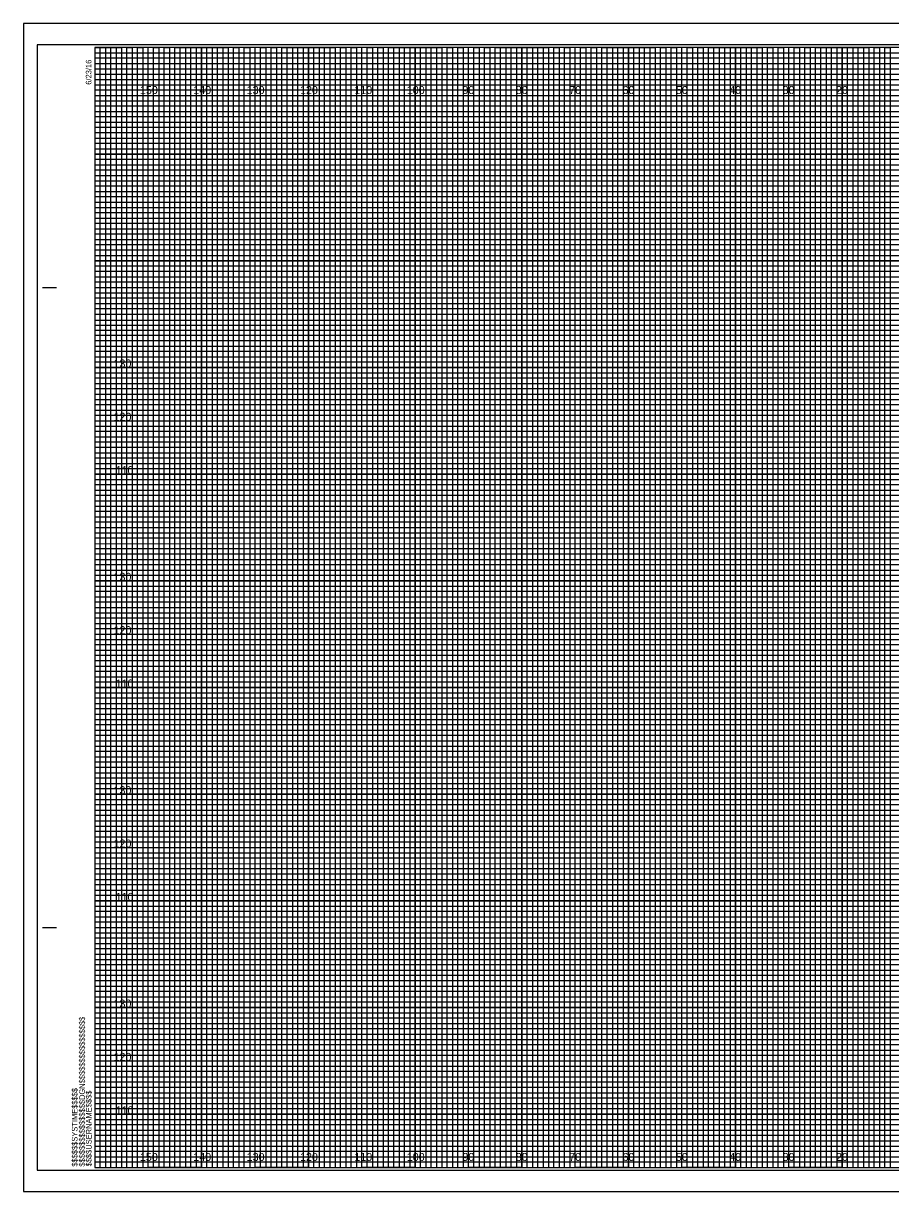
# Model space of a CAD drawing. Extents: x -13 to 323, y -5 to 215.
# Drawn here: x -13.4 to 149.1, y -4.5 to 214.5 of the extents above; entities that cross this region are included whole.
import ezdxf

# ---------------------------------------------------------------- set-up
doc = ezdxf.new("R2010")
doc.units = 0
for name, color, linetype in [('Prop XS Elevation Labels', 7, 'Continuous'), ('Prop XS Offset Labels', 7, 'Continuous'), ('Sheet Cross Section CELL', 7, 'Continuous'), ('Sheet Cross Section Grid Major CELL', 7, 'Continuous'), ('Sheet Cross Section Grid Middle CELL', 7, 'Continuous'), ('Sheet Cross Section Grid Minor 1 CELL', 7, 'Continuous'), ('Sheet Cross Section Grid Minor 2 CELL', 7, 'Continuous'), ('Sheet Cutting Line CELL', 7, 'Continuous'), ('Sheet DOT Grid CELL', 7, 'Continuous'), ('Sheet Plot Border Inside CELL', 7, 'Continuous'), ('Sheet Plot Border Outside CELL', 7, 'Continuous')]:
    doc.layers.add(name, color=color, linetype=linetype)

msp = doc.modelspace()

# ---------------------------------------------------------------- linework, layer by layer
at = {"layer": 'Sheet Cross Section CELL'}
for p, q in [((-9.8, 165), (-7.3, 165)), ((-9.7, 165), (-7.2, 165)), ((-9.8, 45), (-7.3, 45)), ((-9.7, 45), (-7.2, 45)), ((0, 0), (0, 0)), ((0, 0), (0, 0)), ((0, 0), (0, 0)), ((0, 0), (0, 0)), ((0, 0), (0, 0)), ((0, 0), (0, 0)), ((0, 0), (0, 0))]:
    msp.add_line(p, q, dxfattribs=at)
msp.add_lwpolyline([(320, 210), (0, 210), (0, 0), (320, 0)], close=True, dxfattribs=at)
at = {"layer": 'Sheet Cross Section Grid Major CELL'}
for p, q in [((10, 210), (0, 210)), ((10, 0), (10, 210)), ((30, 210), (20, 210)), ((20, 210), (20, 0)), ((30, 0), (30, 210)), ((50, 210), (40, 210)), ((40, 210), (40, 0)), ((50, 0), (50, 210)), ((70, 210), (60, 210)), ((60, 210), (60, 0)), ((70, 0), (70, 210)), ((90, 210), (80, 210)), ((80, 210), (80, 0)), ((90, 0), (90, 210)), ((110, 210), (100, 210)), ((100, 210), (100, 0)), ((110, 0), (110, 210)), ((130, 210), (120, 210)), ((120, 210), (120, 0)), ((130, 0), (130, 210)), ((150, 210), (140, 210)), ((140, 210), (140, 0)), ((20, 0), (10, 0)), ((40, 0), (30, 0)), ((60, 0), (50, 0)), ((80, 0), (70, 0)), ((100, 0), (90, 0)), ((120, 0), (110, 0)), ((140, 0), (130, 0))]:
    msp.add_line(p, q, dxfattribs=at)
for points in [[(0, 200), (320, 200), (320, 190), (0, 190)], [(0, 180), (320, 180), (320, 170), (0, 170)], [(0, 160), (320, 160), (320, 150), (0, 150)], [(0, 140), (320, 140), (320, 130), (0, 130)], [(0, 120), (320, 120), (320, 110), (0, 110)], [(0, 100), (320, 100), (320, 90), (0, 90)], [(0, 80), (320, 80), (320, 70), (0, 70)], [(0, 60), (320, 60), (320, 50), (0, 50)], [(0, 40), (320, 40), (320, 30), (0, 30)], [(0, 20), (320, 20), (320, 10), (0, 10)]]:
    msp.add_lwpolyline(points, dxfattribs=at)
at = {"layer": 'Sheet Cross Section Grid Middle CELL'}
for points in [[(0, 210), (5, 210), (5, 0), (15, 0), (15, 210), (25, 210), (25, 0), (35, 0), (35, 210), (45, 210), (45, 0), (55, 0), (55, 210), (65, 210), (65, 0), (75, 0), (75, 210), (85, 210), (85, 0), (95, 0), (95, 210), (105, 210), (105, 0), (115, 0), (115, 210), (125, 210), (125, 0), (135, 0), (135, 210), (145, 210), (145, 0), (155, 0)], [(0, 205), (275, 205)], [(0, 185), (320, 185), (320, 195), (0, 195)], [(0, 165), (320, 165), (320, 175), (0, 175)], [(0, 145), (320, 145), (320, 155), (0, 155)], [(0, 125), (320, 125), (320, 135), (0, 135)], [(0, 105), (320, 105), (320, 115), (0, 115)], [(0, 85), (320, 85), (320, 95), (0, 95)], [(0, 65), (320, 65), (320, 75), (0, 75)], [(0, 45), (320, 45), (320, 55), (0, 55)], [(0, 25), (320, 25), (320, 35), (0, 35)], [(0, 5), (320, 5), (320, 15), (0, 15)]]:
    msp.add_lwpolyline(points, dxfattribs=at)
at = {"layer": 'Sheet Cross Section Grid Minor 1 CELL'}
for p, q in [((0, 209), (260, 209)), ((260, 207.98), (0, 207.98)), ((0, 207.98), (0, 207)), ((0, 207), (260, 207)), ((260, 205.89), (0, 205.89)), ((0, 205.89), (0, 204)), ((0, 204), (320, 204))]:
    msp.add_line(p, q, dxfattribs=at)
for points in [[(0, 203), (270, 203), (320, 203), (320, 202), (0, 202)], [(0, 201), (320, 201), (320, 199), (0, 199)], [(0, 198), (320, 198), (320, 197), (0, 196.98)], [(0, 196), (320, 196), (320, 194), (0, 194)], [(0, 193), (320, 193), (320, 192), (0, 192)], [(0, 191), (320, 191), (320, 189), (0, 189)], [(0, 188), (320, 188), (320, 187), (0, 187)], [(0, 186), (320, 186), (320, 184), (0, 184)], [(0, 183), (320, 183), (320, 182), (0, 182)], [(0, 181), (320, 181), (320, 179), (0, 179)], [(0, 178), (320, 178), (320, 177), (0, 177)], [(0, 176), (320, 176), (320, 173.95), (320, 173), (320, 172), (0, 172)], [(0, 174), (320, 174), (320, 173), (0, 173)], [(0, 171), (320, 171), (320, 169), (0, 169.03)], [(0, 169.03), (320, 169), (320, 168), (0, 168)], [(0, 167), (320, 167), (320, 166), (0, 166)], [(0, 164), (320, 164), (320, 163), (0, 163)], [(0, 162), (320, 162), (320, 161), (0, 161)], [(-0.07, 158.89), (320, 158.89), (320, 157.88), (-0.07, 157.88)], [(0, 157), (320, 157), (320, 156), (0, 156)], [(0, 154), (320, 154), (320, 153), (0, 153)], [(0, 152), (320, 152), (320, 151), (0, 151)], [(0, 149), (320, 149), (320, 148), (0, 148)], [(0, 147), (320, 147), (320, 146), (0, 146)], [(0, 144), (320, 144), (320, 143), (0, 143)], [(0, 142), (320, 142), (320, 141), (0, 141)], [(0, 139), (320, 139), (319.99, 137.98), (0, 138)], [(0, 137), (320, 137), (320, 136), (0, 136)], [(0, 134), (320, 134), (320, 133), (0, 133)], [(0, 132), (320, 132), (320, 131), (0, 131)], [(0, 129), (320, 129), (320, 128), (0, 128)], [(0, 127), (320, 127), (320, 126), (0, 126)], [(0, 124), (320, 124), (320, 123), (0, 123)], [(0, 122), (320, 122), (320, 121), (0, 121)], [(0, 119), (320, 119), (320, 118), (0, 118)], [(0, 116.99), (320.07, 116.91), (320, 116), (0, 116)], [(0, 114), (320, 114), (320, 113), (0, 113)], [(0, 112), (320, 112), (320, 111), (0, 111)], [(0, 109), (320, 109), (320, 108), (0, 108)], [(0, 107), (320, 107), (320, 106), (0, 106)], [(0, 104), (320, 104), (320, 103), (0, 103)], [(0, 102), (320, 102), (320, 101), (0, 101)], [(0, 99), (320, 99), (320, 98), (0, 98)], [(0, 97), (320, 97), (320, 96), (0, 96)], [(0, 94), (320, 94), (320, 93), (0, 93)], [(0, 92), (320, 92), (320, 91), (0, 91)], [(0, 89), (320, 89), (320, 88), (0, 88)], [(0, 87), (320, 87), (320, 86), (0, 86)], [(0, 84), (320, 84), (320, 83), (0, 83)], [(0, 82), (320, 82), (320, 81), (0, 81)], [(0, 79), (320, 79), (319.99, 77.98), (0, 78)], [(0, 77), (320, 77), (320, 76), (0, 76)], [(0, 74), (320, 74), (320, 73), (0, 73)], [(0, 72), (320, 72), (320, 71), (0, 71)], [(0, 69), (320, 69), (320, 68), (0, 68)], [(0, 67), (320, 67), (320, 66), (0, 66)], [(0, 64), (320, 64), (320, 63), (0, 63)], [(0, 62), (320, 62), (320, 61), (0, 61)], [(0, 59), (320, 59), (320, 58), (0, 58)], [(0, 56.99), (320.07, 56.91), (320, 56), (0, 56)], [(0, 54), (320, 54), (320, 53), (0, 53)], [(0, 52), (320, 52), (320, 51), (0, 51)], [(0, 49), (320, 49), (320, 48), (0, 48)], [(0, 47), (320, 47), (320, 46), (0, 46)], [(0, 44), (320, 44), (320, 43), (0, 43)], [(0, 42), (320, 42), (320, 41), (0, 41)], [(0, 39), (320, 39), (320, 38), (0, 38)], [(0, 37), (320, 37), (320, 36), (0, 36)], [(0, 34), (320, 34), (320, 33), (0, 33)], [(0, 32), (320, 32), (320, 31), (0, 31)], [(0, 29), (320, 29), (320, 28), (0, 28)], [(0, 27), (320, 27), (320, 26), (0, 26)], [(0, 24), (320, 24), (320, 23), (0, 23)], [(0, 22), (320, 22), (320, 21), (0, 21)], [(0, 19), (320, 19), (320, 18), (0, 18)], [(0, 17), (320, 17), (320, 16), (0, 16)], [(0, 14), (320, 14), (320, 13), (0, 13)], [(0, 12), (320, 12), (320, 11), (0, 11)], [(0, 9), (320, 9), (320, 8), (0, 8)], [(0, 7), (320, 7), (320, 6), (0, 6)], [(0, 4), (320, 4), (320, 3), (0, 3)], [(0, 2), (320, 2), (320, 1), (0, 1)]]:
    msp.add_lwpolyline(points, dxfattribs=at)
at = {"layer": 'Sheet Cross Section Grid Minor 2 CELL'}
for points in [[(0, 0), (1, 0), (1, 210), (2, 210), (2, 0)], [(2, 0), (3, 0), (3, 210), (4, 210), (4, 0)], [(5, 0), (6, 0), (6, 210), (7, 210), (7, 0)], [(7, 0), (8, 0), (8, 210), (9, 210), (9, 0)], [(10, 0), (11, 0), (11, 210), (12, 210), (12, 0)], [(12, 0), (13, 0), (13, 210), (14, 210), (14, 0)], [(15, 0), (16, 0), (16, 210), (17, 210), (17, 0)], [(17, 0), (18, 0), (18, 210), (19, 210), (19, 0)], [(20, 0), (21, 0), (21, 210), (22, 210), (22, 0)], [(22, 0), (23, 0), (23, 210), (24, 210), (24, 0)], [(25, 0), (26, 0), (26, 210), (27, 210), (27, 0)], [(27, 0), (28, 0), (28, 210), (29, 210), (29, 0)], [(30, 0), (31, 0), (31, 210), (32, 210), (32, 0)], [(32, 0), (33, 0), (33, 210), (34, 210), (34, 0)], [(35, 0), (36, 0), (36, 210), (37, 210), (37, 0)], [(37, 0), (38, 0), (38, 210), (39, 210), (39, 0)], [(40, 0), (41, 0), (41, 210), (42, 210), (42, 0)], [(42, 0), (43, 0), (43, 210), (44, 210), (44, 0)], [(45, 0), (46, 0), (46, 210), (47, 210), (47, 0)], [(47, 0), (48, 0), (48, 210), (49, 210), (49, 0)], [(50, 0), (51, 0), (51, 210), (52, 210), (52, 0)], [(52, 0), (53, 0), (53, 210), (54, 210), (54, 0)], [(55, 0), (56, 0), (56, 210), (57, 210), (57, 0)], [(57, 0), (58, 0), (58, 210), (59, 210), (59, 0)], [(60, 0), (61, 0), (61, 210), (62, 210), (62, 0)], [(62, 0), (63, 0), (63, 210), (64, 210), (64, 0)], [(65, 0), (66, 0), (66, 210), (67, 210), (67, 0)], [(67, 0), (68, 0), (68, 210), (69, 210), (69, 0)], [(70, 0), (71, 0), (71, 210), (72, 210), (72, 0)], [(72, 0), (73, 0), (73, 210), (74, 210), (74, 0)], [(75, 0), (76, 0), (76, 210), (77, 210), (77, 0)], [(77, 0), (78, 0), (78, 210), (79, 210), (79, 0)], [(80, 0), (81, 0), (81, 210), (82, 210), (82, 0)], [(82, 0), (83, 0), (83, 210), (84, 210), (84, 0)], [(85, 0), (86, 0), (86, 210), (87, 210), (87, 0)], [(87, 0), (88, 0), (88, 210), (89, 210), (89, 0)], [(90, 0), (91, 0), (91, 210), (92, 210), (92, 0)], [(92, 0), (93, 0), (93, 210), (94, 210), (94, 0)], [(95, 0), (96, 0), (96, 210), (97, 210), (97, 0)], [(97, 0), (98, 0), (98, 210), (99, 210), (99, 0)], [(100, 0), (101, 0), (101, 210), (102, 210), (102, 0)], [(102, 0), (103, 0), (103, 210), (104, 210), (104, 0)], [(105, 0), (106, 0), (106, 210), (107, 210), (107, 0)], [(107, 0), (108, 0), (108, 210), (109, 210), (109, 0)], [(110, 0), (111, 0), (111, 210), (112, 210), (112, 0)], [(112, 0), (113, 0), (113, 210), (114, 210), (114, 0)], [(115, 0), (116, 0), (116, 210), (117, 210), (117, 0)], [(117, 0), (118, 0), (118, 210), (119, 210), (119, 0)], [(120, 0), (121, 0), (121, 210), (122, 210), (122, 0)], [(122, 0), (123, 0), (123, 210), (124, 210), (124, 0)], [(125, 0), (126, 0), (126, 210), (127, 210), (127, 0)], [(127, 0), (128, 0), (128, 210), (129, 210), (129, 0)], [(130, 0), (131, 0), (131, 210), (132, 210), (132, 0)], [(132, 0), (133, 0), (133, 210), (134, 210), (134, 0)], [(135, 0), (136, 0), (136, 210), (137, 210), (137, 0)], [(137, 0), (138, 0), (138, 210), (139, 210), (139, 0)], [(140, 0), (141, 0), (141, 210), (142, 210), (142, 0)], [(142, 0), (143, 0), (143, 210), (144, 210), (144, 0)], [(145, 0), (146, 0), (146, 210), (147, 210), (147, 0)], [(147, 0), (148, 0), (148, 210), (149, 210), (149, 0)]]:
    msp.add_lwpolyline(points, dxfattribs=at)
at = {"layer": 'Sheet Cutting Line CELL'}
for p, q in [((323.3, 214.5), (-13.4, 214.5)), ((-13.4, 214.5), (-13.4, -4.5)), ((-13.4, -4.5), (323.3, -4.5))]:
    msp.add_line(p, q, dxfattribs=at)
at = {"layer": 'Sheet DOT Grid CELL'}
for p, q in [((10, 0), (10, 210)), ((20, 0), (20, 210)), ((30, 0), (30, 210)), ((40, 0), (40, 210)), ((50, 0), (50, 210)), ((60, 0), (60, 210)), ((70, 0), (70, 210)), ((80, 0), (80, 210)), ((90, 0), (90, 210)), ((100, 0), (100, 210)), ((110, 0), (110, 210)), ((120, 0), (120, 210)), ((130, 0), (130, 210)), ((140, 0), (140, 210)), ((0, 200), (320, 200)), ((0, 190), (320, 190)), ((0, 180), (320, 180)), ((0, 170), (320, 170)), ((0, 160), (320, 160)), ((0, 150), (320, 150)), ((0, 140), (320, 140)), ((0, 130), (320, 130)), ((0, 120), (320, 120)), ((0, 110), (320, 110)), ((0, 100), (320, 100)), ((0, 90), (320, 90)), ((0, 80), (320, 80)), ((0, 70), (320, 70)), ((0, 60), (320, 60)), ((0, 50), (320, 50)), ((0, 40), (320, 40)), ((0, 30), (320, 30)), ((0, 20), (320, 20)), ((0, 10), (320, 10))]:
    msp.add_line(p, q, dxfattribs=at)
at = {"layer": 'Sheet Plot Border Inside CELL'}
msp.add_lwpolyline([(-10.8, -0.5), (322.4, -0.5), (322.4, 210.5), (-10.8, 210.5)], close=True, dxfattribs=at)
at = {"layer": 'Sheet Plot Border Outside CELL'}
msp.add_lwpolyline([(-13.4, -4.5), (323.3, -4.5), (323.3, 214.5), (-13.4, 214.5)], close=True, dxfattribs=at)

# ---------------------------------------------------------------- texts
at = {"layer": 'Prop XS Elevation Labels'}
for s, p in [('130', (3.49, 150)), ('120', (3.5, 140)), ('110', (3.88, 130)), ('130', (3.49, 110)), ('120', (3.5, 100)), ('110', (3.88, 90)), ('130', (3.49, 70)), ('120', (3.5, 60)), ('110', (3.88, 50)), ('130', (3.49, 30)), ('120', (3.5, 20)), ('110', (3.88, 10))]:
    msp.add_text(s, height=1.5, dxfattribs=at).set_placement(p)
at = {"layer": 'Prop XS Offset Labels'}
for s, p in [('150', (8.44, 201.25)), ('140', (18.44, 201.25)), ('130', (28.44, 201.25)), ('120', (38.44, 201.25)), ('110', (48.62, 201.25)), ('100', (58.44, 201.25)), ('90', (68.86, 201.25)), ('80', (78.86, 201.25)), ('70', (88.86, 201.25)), ('60', (98.86, 201.25)), ('50', (108.86, 201.25)), ('40', (118.86, 201.25)), ('30', (128.86, 201.25)), ('20', (138.86, 201.25)), ('150', (8.44, 1.25)), ('140', (18.44, 1.25)), ('130', (28.44, 1.25)), ('120', (38.44, 1.25)), ('110', (48.62, 1.25)), ('100', (58.44, 1.25)), ('90', (68.86, 1.25)), ('80', (78.86, 1.25)), ('70', (88.86, 1.25)), ('60', (98.86, 1.25)), ('50', (108.86, 1.25)), ('40', (118.86, 1.25)), ('30', (128.86, 1.25)), ('20', (138.86, 1.25))]:
    msp.add_text(s, height=1.5, dxfattribs=at).set_placement(p)
at = {"layer": 'Sheet Cross Section CELL'}
for s, p in [('6/23/16', (-0.65, 203)), ('$$$$$$$$$$$$$$$$DGN$$$$$$$$$$$$$$$$', (-1.88, 0.18)), ('$$$$$$SYSTIME$$$$$', (-3.26, 0.18)), ('$$$$USERNAME$$$$', (-0.62, 0.23))]:
    msp.add_text(s, height=1.05, rotation=90, dxfattribs=at).set_placement(p)

doc.saveas('drawing.dxf')
